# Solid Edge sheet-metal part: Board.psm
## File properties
Author: conerly
Template: ansi sheet metal.psm
Last saved by: alogan
Revision: 34
Application: Solid Edge
Density: 0.0979772159 lbm/in^3
Accuracy: 0.990
Material Thickness: 0.125 in
Bend Radius: 0.125 in
Relief Width: 0.125 in
Relief Length: 0.125 in
Neutral Factor: 0.330
Minimum Arc Length: 0.005 in
Deviational Tolerance: 0.005 in
Material: Aluminum, 1060
Face Style: Aluminum
Fill Style: ANSI38(Aluminum)
Virtual Style: Polished aluminum
Coef. of Thermal Exp: 2.3e-05
Thermal Conductivity: 221.0
Specific Heat: 920.0
Modulus of Elasticity: 68947570000.0
Poisson's Ratio: 0.33
Yield Stress: 27579028.0
Ultimate Stress: 68947570.0
Elongation: 0.0
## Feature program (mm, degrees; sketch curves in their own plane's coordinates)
base tab "unnamed BaseTab 1"
flange "Flange_1"
flange "Flange_2"
flange "Flange_3"
flange "Flange_4"
sketch for "Hole_1" plane through (3.175, -609.6, -106.3625) normal (0, -1, 0) x-axis (1, 0, 0)
hole "Hole_1"
sketch for "Hole_2" plane through (-114.3, 76.2, 3.175) normal (0, 0, 1) x-axis (1, 0, 0)
  hole centre (-610.1736, -610.1736) bore radius 19.05
hole "Hole_2"
flange "Flange_5"
flange "Flange_6"
sketch for "ExtrudedCutout_1" plane through (-114.3, 76.2, 3.175) normal (0, 0, 1) x-axis (1, 0, 0)
  bspline degree 3 poles (436.562, 570.0215) (486.4885, 470.1611) (389.4528, 372.6415) (482.4301, 258.6885) (397.7229, 116.5915) (315.6476, -65.3133) (162.5598, -198.8693) (149.5108, -439.8004) (-78.2215, -425.8414) (-102.2775, -631.9981) (-190.9565, -696.0843) (-244.9824, -747.1203) knots 0 0.1107 0.2088 0.3073 0.4167 0.5753 0.6742 0.7905 0.8747 1 multiplicities 4 1 1 1 1 1 1 1 1 4
extrude "ExtrudedCutout_1" cut
sketch for "Hole_3" plane through (-1195.3875, -766.7625, -3.175) normal (0, 0, 1) x-axis (1, 0, 0)
  hole centre (-12.0699, 58.9703) bore radius 19.05
hole "Hole_3"
sketch for "Hole_4" plane through (-911.225, -766.7625, -109.5375) normal (1, 0, 0) x-axis (0, 1, 0)
  hole centre (91.6071, 44.1237) bore radius 19.05
hole "Hole_4"
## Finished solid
Body 1: solid body, 48 faces, 126 edges, 76 vertices.
  Faces by surface: plane 31, cylinder 16, swept 1
  Edges by curve: line 91, circle 30, spline 3, intersection 2
Bounding box of the edges (mm; curved faces can reach further): 1823.350 x 1682.750 x 396.875, from (-1479.55, -920.75, -209.55) to (343.7999, 762, 187.325).
Cylindrical faces by radius (mm): R3.175 x6, R6.35 x6, R19.05 x4
Planar faces by outward normal: +x 4, +y 6, +z 6, -x 7, -y 5, -z 3
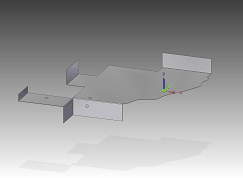
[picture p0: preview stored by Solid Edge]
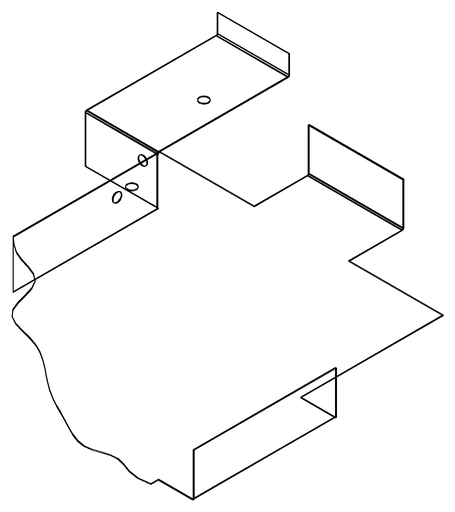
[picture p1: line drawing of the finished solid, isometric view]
